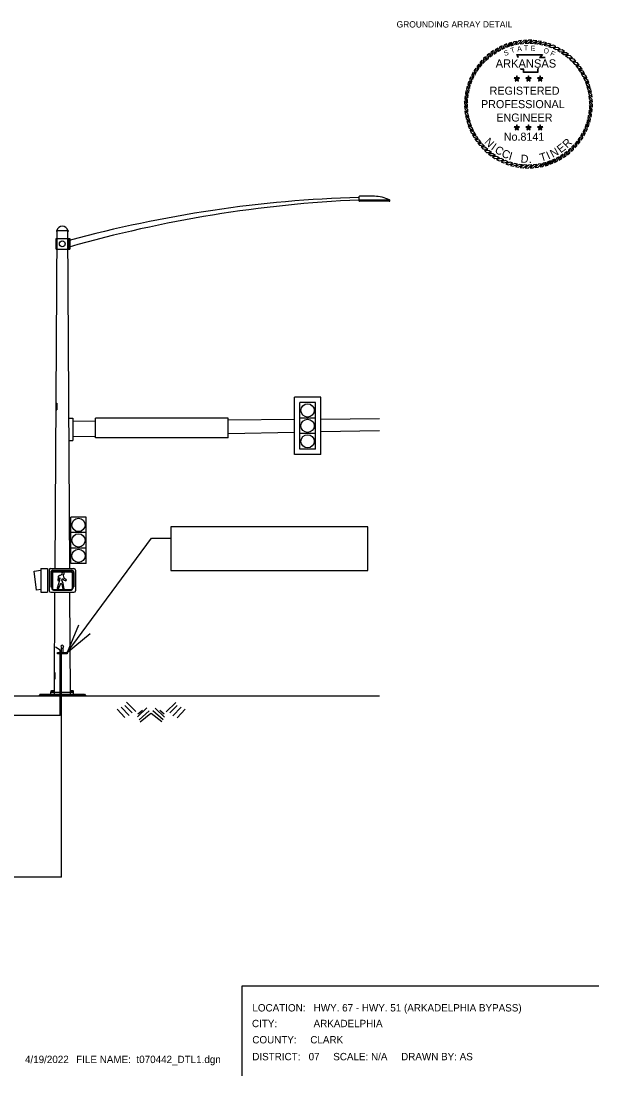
# Model space of a CAD drawing. Extents: x 418532 to 419834, y -565899 to -565296.
# Drawn here: x 419505 to 419834, y -565899 to -565297 of the extents above; entities that cross this region are included whole.
import ezdxf

# ---------------------------------------------------------------- set-up
doc = ezdxf.new("R2010")
doc.units = 0
for name, color, linetype in [('G-ANNO-SYMB', 7, 'Continuous'), ('G-ANNO-TEXT', 7, 'Continuous'), ('Level 10', 7, 'Continuous'), ('Level 57', 7, 'Continuous'), ('R_Draft', 7, 'Continuous'), ('T_Drafting', 7, 'Continuous')]:
    doc.layers.add(name, color=color, linetype=linetype)

msp = doc.modelspace()

# ---------------------------------------------------------------- linework, layer by layer
at = {"layer": 'G-ANNO-SYMB'}
for points in [[(419792.99, -565307.49), (419791.42, -565307.57), (419789.36, -565309.46), (419791.04, -565309.28)], [(419795.85, -565307.53), (419794.28, -565307.48), (419792.08, -565309.2), (419793.77, -565309.15)], [(419798.7, -565307.78), (419797.14, -565307.61), (419794.81, -565309.16), (419796.5, -565309.24)], [(419774.09, -565313.41), (419772.79, -565314.3), (419772.02, -565316.99), (419773.36, -565315.95)], [(419776.55, -565311.94), (419775.19, -565312.72), (419774.21, -565315.34), (419775.62, -565314.41)], [(419779.11, -565310.67), (419777.69, -565311.34), (419776.51, -565313.87), (419778, -565313.06)], [(419781.77, -565309.6), (419780.3, -565310.16), (419778.93, -565312.59), (419780.47, -565311.9)], [(419784.5, -565308.75), (419783, -565309.19), (419781.43, -565311.51), (419783.03, -565310.93)], [(419787.29, -565308.11), (419785.76, -565308.43), (419784.02, -565310.62), (419785.65, -565310.17)], [(419790.13, -565307.69), (419788.57, -565307.89), (419786.67, -565309.93), (419788.33, -565309.62)], [(419801.53, -565308.26), (419799.98, -565307.97), (419797.54, -565309.32), (419799.22, -565309.54)], [(419804.3, -565308.96), (419802.79, -565308.55), (419800.24, -565309.71), (419801.9, -565310.05)], [(419807.02, -565309.87), (419805.54, -565309.34), (419802.91, -565310.3), (419804.54, -565310.77)], [(419809.65, -565311), (419808.22, -565310.35), (419805.53, -565311.1), (419807.11, -565311.7)], [(419812.19, -565312.32), (419810.81, -565311.57), (419808.07, -565312.1), (419809.6, -565312.83)], [(419814.62, -565313.85), (419813.3, -565312.99), (419810.52, -565313.3), (419812, -565314.14)], [(419767.51, -565318.91), (419766.46, -565320.07), (419766.33, -565322.87), (419767.39, -565321.54)], [(419769.56, -565316.91), (419768.42, -565317.98), (419768.07, -565320.76), (419769.23, -565319.52)], [(419771.75, -565315.07), (419770.53, -565316.06), (419769.97, -565318.79), (419771.23, -565317.65)], [(419816.91, -565315.55), (419815.67, -565314.6), (419812.88, -565314.69), (419814.28, -565315.65)], [(419819.07, -565317.44), (419817.91, -565316.38), (419815.12, -565316.26), (419816.44, -565317.32)], [(419821.08, -565319.48), (419820, -565318.34), (419817.22, -565318), (419818.46, -565319.16)], [(419763.92, -565323.37), (419763.06, -565324.68), (419763.38, -565327.46), (419764.22, -565325.99)], [(419765.63, -565321.07), (419764.67, -565322.31), (419764.77, -565325.1), (419765.72, -565323.7)], [(419822.91, -565321.68), (419821.93, -565320.46), (419819.19, -565319.9), (419820.33, -565321.16)], [(419824.57, -565324.02), (419823.68, -565322.72), (419821, -565321.95), (419822.04, -565323.29)], [(419826.04, -565326.47), (419825.26, -565325.11), (419822.64, -565324.13), (419823.57, -565325.55)], [(419759.94, -565330.97), (419759.42, -565332.44), (419760.37, -565335.07), (419760.85, -565333.44)], [(419761.07, -565328.33), (419760.43, -565329.76), (419761.17, -565332.46), (419761.77, -565330.87)], [(419762.4, -565325.79), (419761.64, -565327.17), (419762.18, -565329.91), (419762.9, -565328.38)], [(419787.36, -565329.43), (419786.98, -565328.92), (419785.77, -565328.92), (419786.75, -565329.63)], [(419787.36, -565329.43), (419786.75, -565329.63), (419786.38, -565330.78), (419787.36, -565330.07)], [(419787.36, -565329.43), (419787.73, -565328.92), (419787.36, -565327.76), (419786.98, -565328.92)], [(419787.36, -565329.43), (419787.96, -565329.63), (419788.94, -565328.92), (419787.73, -565328.92)], [(419787.36, -565329.43), (419787.36, -565330.07), (419788.34, -565330.78), (419787.96, -565329.63)], [(419794.03, -565329.43), (419793.65, -565328.92), (419792.44, -565328.92), (419793.42, -565329.63)], [(419794.03, -565329.43), (419793.42, -565329.63), (419793.05, -565330.78), (419794.03, -565330.07)], [(419794.03, -565329.43), (419794.4, -565328.92), (419794.03, -565327.76), (419793.65, -565328.92)], [(419794.03, -565329.43), (419794.63, -565329.63), (419795.61, -565328.92), (419794.4, -565328.92)], [(419794.03, -565329.43), (419794.03, -565330.07), (419795.01, -565330.78), (419794.63, -565329.63)], [(419800.7, -565329.43), (419800.32, -565328.92), (419799.11, -565328.92), (419800.09, -565329.63)], [(419800.7, -565329.43), (419800.09, -565329.63), (419799.72, -565330.78), (419800.7, -565330.07)], [(419800.7, -565329.43), (419801.07, -565328.92), (419800.7, -565327.76), (419800.32, -565328.92)], [(419800.7, -565329.43), (419801.3, -565329.63), (419802.28, -565328.92), (419801.07, -565328.92)], [(419800.7, -565329.43), (419800.7, -565330.07), (419801.68, -565330.78), (419801.3, -565329.63)], [(419827.31, -565329.04), (419826.64, -565327.62), (419824.11, -565326.44), (419824.92, -565327.93)], [(419828.38, -565331.7), (419827.82, -565330.23), (419825.39, -565328.85), (419826.09, -565330.4)], [(419829.24, -565334.43), (419828.8, -565332.92), (419826.48, -565331.36), (419827.05, -565332.96)], [(419758.33, -565336.46), (419758.04, -565338), (419759.4, -565340.44), (419759.61, -565338.76)], [(419759.03, -565333.68), (419758.62, -565335.19), (419759.78, -565337.74), (419760.12, -565336.08)], [(419829.88, -565337.22), (419829.55, -565335.69), (419827.37, -565333.95), (419827.81, -565335.58)], [(419830.29, -565340.06), (419830.09, -565338.5), (419828.05, -565336.59), (419828.37, -565338.26)], [(419757.6, -565342.13), (419757.55, -565343.7), (419759.27, -565345.9), (419759.22, -565344.21)], [(419757.85, -565339.28), (419757.69, -565340.84), (419759.23, -565343.17), (419759.31, -565341.48)], [(419830.49, -565342.91), (419830.41, -565341.35), (419828.52, -565339.28), (419828.71, -565340.97)], [(419830.46, -565345.78), (419830.5, -565344.21), (419828.78, -565342.01), (419828.83, -565343.7)], [(419757.57, -565345), (419757.65, -565346.56), (419759.53, -565348.63), (419759.35, -565346.94)], [(419757.76, -565347.85), (419757.96, -565349.41), (419760.01, -565351.32), (419759.69, -565349.65)], [(419829.72, -565351.45), (419830.01, -565349.91), (419828.66, -565347.47), (419828.45, -565349.15)], [(419830.2, -565348.63), (419830.37, -565347.07), (419828.83, -565344.74), (419828.75, -565346.43)], [(419758.18, -565350.69), (419758.5, -565352.22), (419760.69, -565353.96), (419760.24, -565352.33)], [(419758.82, -565353.48), (419759.26, -565354.99), (419761.58, -565356.55), (419761, -565354.95)], [(419787.36, -565357.36), (419787.73, -565356.84), (419787.36, -565355.69), (419786.98, -565356.84)], [(419794.03, -565357.36), (419794.4, -565356.84), (419794.03, -565355.69), (419793.65, -565356.84)], [(419800.7, -565357.36), (419801.07, -565356.84), (419800.7, -565355.69), (419800.32, -565356.84)], [(419826.99, -565359.58), (419827.63, -565358.15), (419826.88, -565355.45), (419826.28, -565357.04)], [(419828.11, -565356.94), (419828.64, -565355.47), (419827.68, -565352.84), (419827.21, -565354.47)], [(419829.03, -565354.23), (419829.43, -565352.72), (419828.28, -565350.17), (419827.93, -565351.83)], [(419759.67, -565356.21), (419760.23, -565357.68), (419762.67, -565359.06), (419761.97, -565357.51)], [(419760.74, -565358.87), (419761.41, -565360.29), (419763.95, -565361.47), (419763.13, -565359.98)], [(419762.01, -565361.44), (419762.8, -565362.8), (419765.41, -565363.78), (419764.48, -565362.36)], [(419787.36, -565357.36), (419786.98, -565356.84), (419785.77, -565356.84), (419786.75, -565357.56)], [(419787.36, -565357.36), (419786.75, -565357.56), (419786.38, -565358.71), (419787.36, -565358)], [(419787.36, -565357.36), (419787.96, -565357.56), (419788.94, -565356.84), (419787.73, -565356.84)], [(419787.36, -565357.36), (419787.36, -565358), (419788.34, -565358.71), (419787.96, -565357.56)], [(419794.03, -565357.36), (419793.65, -565356.84), (419792.44, -565356.84), (419793.42, -565357.56)], [(419794.03, -565357.36), (419793.42, -565357.56), (419793.05, -565358.71), (419794.03, -565358)], [(419794.03, -565357.36), (419794.63, -565357.56), (419795.61, -565356.84), (419794.4, -565356.84)], [(419794.03, -565357.36), (419794.03, -565358), (419795.01, -565358.71), (419794.63, -565357.56)], [(419800.7, -565357.36), (419800.32, -565356.84), (419799.11, -565356.84), (419800.09, -565357.56)], [(419800.7, -565357.36), (419800.09, -565357.56), (419799.72, -565358.71), (419800.7, -565358)], [(419800.7, -565357.36), (419801.3, -565357.56), (419802.28, -565356.84), (419801.07, -565356.84)], [(419800.7, -565357.36), (419800.7, -565358), (419801.68, -565358.71), (419801.3, -565357.56)], [(419824.14, -565364.54), (419824.99, -565363.23), (419824.68, -565360.45), (419823.84, -565361.92)], [(419825.66, -565362.12), (419826.41, -565360.74), (419825.88, -565358), (419825.16, -565359.53)], [(419763.48, -565363.89), (419764.37, -565365.19), (419767.06, -565365.96), (419766.02, -565364.62)], [(419765.14, -565366.23), (419766.13, -565367.45), (419768.87, -565368.01), (419767.73, -565366.75)], [(419818.5, -565371), (419819.64, -565369.93), (419819.98, -565367.15), (419818.82, -565368.39)], [(419820.55, -565369), (419821.6, -565367.84), (419821.72, -565365.04), (419820.66, -565366.37)], [(419822.43, -565366.84), (419823.39, -565365.6), (419823.29, -565362.81), (419822.34, -565364.21)], [(419766.98, -565368.43), (419768.06, -565369.57), (419770.83, -565369.91), (419769.6, -565368.75)], [(419768.98, -565370.47), (419770.15, -565371.53), (419772.94, -565371.65), (419771.62, -565370.59)], [(419771.14, -565372.36), (419772.38, -565373.31), (419775.18, -565373.22), (419773.78, -565372.26)], [(419773.44, -565374.06), (419774.75, -565374.92), (419777.53, -565374.61), (419776.06, -565373.77)], [(419811.51, -565375.97), (419812.87, -565375.19), (419813.85, -565372.57), (419812.43, -565373.5)], [(419813.97, -565374.5), (419815.26, -565373.61), (419816.03, -565370.93), (419814.69, -565371.96)], [(419816.3, -565372.84), (419817.52, -565371.85), (419818.08, -565369.12), (419816.83, -565370.26)], [(419775.87, -565375.59), (419777.24, -565376.34), (419779.99, -565375.81), (419778.45, -565375.08)], [(419778.4, -565376.91), (419779.84, -565377.56), (419782.53, -565376.81), (419780.94, -565376.21)], [(419781.04, -565378.04), (419782.52, -565378.57), (419785.14, -565377.61), (419783.51, -565377.14)], [(419783.75, -565378.95), (419785.27, -565379.36), (419787.81, -565378.2), (419786.15, -565377.86)], [(419786.53, -565379.65), (419788.07, -565379.94), (419790.52, -565378.59), (419788.84, -565378.37)], [(419789.35, -565380.13), (419790.91, -565380.3), (419793.24, -565378.75), (419791.55, -565378.67)], [(419792.21, -565380.38), (419793.77, -565380.43), (419795.98, -565378.71), (419794.28, -565378.76)], [(419795.07, -565380.42), (419796.64, -565380.34), (419798.7, -565378.45), (419797.01, -565378.63)], [(419797.93, -565380.22), (419799.48, -565380.02), (419801.39, -565377.98), (419799.73, -565378.29)], [(419800.76, -565379.8), (419802.3, -565379.48), (419804.04, -565377.29), (419802.4, -565377.74)], [(419803.55, -565379.16), (419805.06, -565378.72), (419806.62, -565376.4), (419805.03, -565376.98)], [(419806.29, -565378.31), (419807.75, -565377.75), (419809.13, -565375.32), (419807.58, -565376.01)], [(419808.94, -565377.24), (419810.36, -565376.57), (419811.54, -565374.04), (419810.06, -565374.85)]]:
    msp.add_lwpolyline(points, close=True, dxfattribs=at)
for points in [[(419788.18, -565317.48), (419787.33, -565315.64), (419802.05, -565315.63), (419800.82, -565317.18), (419801.82, -565317.16), (419802.65, -565317.15), (419803.49, -565317.24)], [(419788.4, -565317.38), (419787.7, -565315.87), (419801.56, -565315.87), (419800.33, -565317.42), (419801.82, -565317.4), (419802.64, -565317.39), (419803.46, -565317.48)], [(419799.73, -565323.65), (419799.48, -565323.85), (419799.39, -565324.16), (419799.31, -565324.92), (419799.31, -565325.94), (419791.1, -565325.94), (419791.1, -565324.56), (419791.1, -565324.26), (419790.76, -565324.16), (419789.6, -565324.16), (419789.39, -565323.84)], [(419799.58, -565323.47), (419799.27, -565323.72), (419799.16, -565324.11), (419799.08, -565324.91), (419799.08, -565325.7), (419791.33, -565325.7), (419791.33, -565324.56), (419791.33, -565324.09), (419790.8, -565323.92), (419789.72, -565323.92), (419789.58, -565323.71)]]:
    msp.add_lwpolyline(points, dxfattribs=at)
at = {"layer": 'Level 57'}
for points in [[(419630.59, -565847.55), (419630.59, -565898.75)], [(419834.17, -565847.55), (419630.59, -565847.55)]]:
    msp.add_lwpolyline(points, dxfattribs=at)
at = {"layer": 'R_Draft'}
for p, q in [((419530.89, -565657.08), (419578.95, -565591.72)), ((419578.95, -565591.72), (419589.97, -565591.72))]:
    msp.add_line(p, q, dxfattribs=at)
msp.add_lwpolyline([(419589.97, -565610.25), (419702.39, -565610.25), (419702.39, -565585.34), (419589.97, -565585.34)], close=True, dxfattribs=at)
msp.add_lwpolyline([(419537.34, -565641.34), (419530.89, -565657.08), (419543.99, -565646.23)], dxfattribs=at)
at = {"layer": 'T_Drafting'}
for p, q in [((419697.33, -565396.95), (419697.33, -565397.22)), ((419697.33, -565397.22), (419697.33, -565399.07)), ((419706.15, -565396.57), (419697.71, -565396.57)), ((419714.89, -565398.73), (419697.33, -565398.73)), ((419714.6, -565399.44), (419697.71, -565399.44)), ((419714.98, -565398.97), (419714.98, -565399.07)), ((419524.99, -565416.17), (419523.86, -565609.16)), ((419524.71, -565420.67), (419531.37, -565420.67)), ((419524.71, -565426.8), (419524.71, -565420.67)), ((419524.84, -565416.17), (419531.49, -565416.17)), ((419524.84, -565416.17), (419524.84, -565416.64)), ((419532.47, -565609.16), (419531.34, -565416.17)), ((419531.37, -565420.67), (419532.51, -565420.67)), ((419531.49, -565416.17), (419531.49, -565416.64)), ((419532.04, -565426.8), (419532, -565420.67)), ((419532.51, -565420.67), (419532.51, -565426.8)), ((419524.75, -565426.8), (419531.41, -565426.8)), ((419531.41, -565426.8), (419532.51, -565426.8)), ((419660.5, -565544), (419660.5, -565511.23)), ((419675.65, -565511.23), (419660.5, -565511.23)), ((419675.65, -565544), (419675.65, -565511.23)), ((419524.41, -565514.72), (419525.01, -565514.72)), ((419525.01, -565514.72), (419524.99, -565518.51)), ((419663.65, -565540.85), (419663.65, -565514.38)), ((419672.5, -565514.38), (419663.65, -565514.38)), ((419672.5, -565540.85), (419672.5, -565514.38)), ((419524.39, -565518.51), (419524.99, -565518.51)), ((419531.97, -565523.22), (419534.21, -565523.22)), ((419534.21, -565523.22), (419534.21, -565536)), ((419622.72, -565523.19), (419547.1, -565523.19)), ((419547.1, -565534.53), (419547.1, -565523.19)), ((419622.72, -565534.53), (419622.72, -565523.19)), ((419660.5, -565524.06), (419622.72, -565524.39)), ((419672.5, -565523.2), (419663.65, -565523.2)), ((419709.07, -565523.64), (419675.65, -565523.93)), ((419547.1, -565525.05), (419534.21, -565525.17)), ((419709.07, -565530.39), (419675.65, -565531.08)), ((419532.04, -565536), (419534.21, -565536)), ((419547.1, -565533.72), (419534.21, -565533.99)), ((419622.72, -565534.53), (419547.1, -565534.53)), ((419660.5, -565531.39), (419622.72, -565532.17)), ((419672.5, -565532.03), (419663.65, -565532.03)), ((419672.5, -565540.85), (419663.65, -565540.85)), ((419675.65, -565544), (419660.5, -565544)), ((419533, -565606.24), (419533, -565579.77)), ((419541.85, -565579.77), (419533, -565579.77)), ((419541.85, -565606.24), (419541.85, -565579.77)), ((419541.85, -565588.59), (419533, -565588.59)), ((419541.85, -565597.42), (419533, -565597.42)), ((419541.85, -565606.24), (419533, -565606.24)), ((419512.13, -565610.68), (419515.92, -565610.07)), ((419513.39, -565621.37), (419512.13, -565610.68)), ((419515.92, -565609.16), (419515.92, -565622.64)), ((419515.92, -565609.16), (419519.7, -565609.16)), ((419519.7, -565609.16), (419519.7, -565622.64)), ((419520.6, -565610.07), (419520.6, -565621.69)), ((419521.51, -565609.16), (419534.82, -565609.16)), ((419521.55, -565611.36), (419521.55, -565619.49)), ((419522.19, -565611.58), (419522.19, -565620.46)), ((419522.49, -565611.58), (419522.49, -565620.46)), ((419522.84, -565610.07), (419533.46, -565610.07)), ((419523.1, -565610.68), (419533.23, -565610.68)), ((419523.1, -565610.98), (419533.23, -565610.98)), ((419533.84, -565611.58), (419533.84, -565620.46)), ((419534.14, -565611.58), (419534.14, -565620.46)), ((419534.75, -565611.36), (419534.75, -565619.49)), ((419535.73, -565610.07), (419535.73, -565621.73)), ((419521.55, -565619.49), (419522.18, -565619.49)), ((419534.14, -565619.49), (419534.75, -565619.49)), ((419515.92, -565621.06), (419513.39, -565621.37)), ((419515.92, -565622.64), (419519.7, -565622.64)), ((419521.55, -565622.64), (419534.82, -565622.64)), ((419523.1, -565621.06), (419533.23, -565621.06)), ((419523.1, -565621.37), (419533.23, -565621.37)), ((419523.78, -565622.64), (419523.44, -565680.86)), ((419532.89, -565680.86), (419532.55, -565622.64)), ((419527.47, -565653.82), (419527.79, -565654.68)), ((419526.94, -565693.03), (419526.94, -565657.87)), ((419527.79, -565785.2), (419527.79, -565657.87)), ((419523.51, -565668.41), (419524, -565668.41)), ((419524, -565668.41), (419523.98, -565672.19)), ((419523.49, -565672.19), (419523.98, -565672.19)), ((419515.56, -565680.86), (419514.93, -565681.49)), ((419515.56, -565680.86), (419540.77, -565680.86)), ((419521.7, -565679.76), (419534.63, -565679.76)), ((419521.7, -565680.86), (419521.7, -565679.76)), ((419521.85, -565678.97), (419523.42, -565678.97)), ((419521.85, -565679.76), (419521.85, -565678.97)), ((419522.07, -565678.65), (419523.2, -565678.65)), ((419522.07, -565678.97), (419522.07, -565678.65)), ((419522.38, -565679.76), (419522.38, -565678.97)), ((419522.91, -565679.76), (419522.91, -565678.97)), ((419523.2, -565678.97), (419523.2, -565678.65)), ((419523.42, -565679.76), (419523.42, -565678.97)), ((419532.92, -565678.97), (419534.48, -565678.97)), ((419532.92, -565679.76), (419532.92, -565678.97)), ((419533.07, -565678.97), (419533.07, -565678.65)), ((419533.07, -565678.65), (419534.33, -565678.65)), ((419533.42, -565679.76), (419533.42, -565678.97)), ((419533.95, -565679.76), (419533.95, -565678.97)), ((419534.33, -565678.97), (419534.33, -565678.65)), ((419534.48, -565679.76), (419534.48, -565678.97)), ((419534.63, -565680.86), (419534.63, -565679.76)), ((419540.77, -565680.86), (419541.4, -565681.49)), ((419709.07, -565681.87), (419149.59, -565681.87)), ((419514.93, -565681.49), (419541.4, -565681.49)), ((419514.93, -565681.87), (419514.93, -565681.49)), ((419541.4, -565681.87), (419541.4, -565681.49)), ((419570.1, -565690.73), (419564.74, -565685.36)), ((419587.47, -565690.84), (419592.83, -565685.48)), ((419563.8, -565694.23), (419559.37, -565689.33)), ((419566.37, -565693.06), (419561.71, -565688.16)), ((419568, -565691.43), (419563.8, -565687.23)), ((419571.03, -565693.76), (419576.39, -565688.63)), ((419571.26, -565692.13), (419573.83, -565690.03)), ((419571.96, -565695.39), (419577.79, -565690.26)), ((419572.66, -565696.56), (419578.73, -565691.66)), ((419584.9, -565696.68), (419578.84, -565691.78)), ((419585.6, -565695.51), (419579.78, -565690.38)), ((419586.54, -565693.88), (419581.17, -565688.74)), ((419586.3, -565692.24), (419583.74, -565690.14)), ((419589.57, -565691.54), (419593.76, -565687.34)), ((419591.2, -565693.18), (419595.86, -565688.28)), ((419593.76, -565694.34), (419598.19, -565689.44)), ((419526.94, -565693.03), (419451.45, -565693.03)), ((419527.79, -565785.2), (419288.41, -565785.2))]:
    msp.add_line(p, q, dxfattribs=at)
for points in [[(419525.77, -565613.59), (419525.65, -565615.91), (419526.37, -565615.91), (419526.55, -565614.38), (419526.72, -565614.38), (419526.54, -565615.74), (419526.54, -565615.98), (419525.32, -565620.28), (419525.32, -565620.44), (419525.81, -565620.82), (419526.02, -565620.65), (419527.31, -565617.4), (419527.84, -565618.01), (419528.47, -565620.88), (419529.28, -565620.61), (419528.71, -565617.57), (419527.93, -565615.76), (419528.44, -565614.84), (419528.8, -565615.51), (419530.24, -565616.07), (419530.52, -565615.68), (419529.15, -565614.53), (419528.8, -565613.08), (419528.86, -565612.87), (419528.86, -565612.64), (419528.93, -565612.6)], [(419526.94, -565657.08), (419526.94, -565655.63), (419524.33, -565653.89)], [(419527.79, -565657.08), (419527.79, -565654.63), (419527.79, -565654.91), (419527.75, -565654.95), (419527.76, -565654.94)], [(419528.76, -565653.82), (419528.46, -565654.61), (419528.46, -565654.61), (419528.46, -565657.08)]]:
    msp.add_lwpolyline(points, dxfattribs=at)
msp.add_lwpolyline([(419525.44, -565657.08), (419530.89, -565657.08), (419530.89, -565657.87), (419525.44, -565657.87)], close=True, dxfattribs=at)
for centre, radius in [((419528.17, -565423.73), 1.66), ((419668.07, -565518.8), 3.78), ((419668.07, -565527.63), 3.78), ((419668.07, -565536.45), 3.78), ((419537.42, -565584.2), 3.78), ((419537.42, -565593.02), 3.78), ((419537.42, -565601.84), 3.78)]:
    msp.add_circle(centre, radius, dxfattribs=at)
for centre, radius, start, end in [((419718.38, -566105.7), 708.8, 91.70171, 105.2447), ((419697.71, -565396.95), 0.378, 90, 180), ((419705.36, -565418.96), 22.41, 65.20004, 87.96446), ((419727.94, -566108.25), 710.19, 92.47054, 106.01353), ((419697.71, -565399.07), 0.378, 180, 270), ((419714.6, -565399.07), 0.378, 270, 0), ((419714.6, -565398.97), 0.378, 360, 65.20004), ((419528.17, -565416.91), 3.26, 13.14148, 166.85852), ((419521.51, -565610.07), 0.907, 90, 180), ((419522.84, -565611.36), 1.29, 90, 180), ((419523.1, -565611.58), 0.907, 90, 180), ((419523.1, -565611.58), 0.605, 90, 180), ((419533.23, -565611.58), 0.907, 0, 90), ((419533.23, -565611.58), 0.605, 0, 90), ((419533.46, -565611.36), 1.29, 0, 90), ((419534.82, -565610.07), 0.907, 0, 90), ((419523.1, -565620.46), 0.907, 180, 270), ((419523.1, -565620.46), 0.605, 180, 270), ((419533.23, -565620.46), 0.605, 270, 0), ((419533.23, -565620.46), 0.907, 270, 0), ((419521.55, -565621.69), 0.945, 180, 270), ((419534.82, -565621.73), 0.907, 270, 0), ((419528.12, -565653.52), 0.721, 336.80141, 203.80594), ((419528.12, -565653.52), 0.721, 239.53446, 239.74356)]:
    msp.add_arc(centre, radius, start, end, dxfattribs=at)
msp.add_ellipse((419528.62, -565611.91), major_axis=(0, -0.761), ratio=0.9, start_param=0.463156, end_param=5.216339, dxfattribs=at)
msp.add_spline([(419528.02, -565612.28), (419527.95, -565612.41), (419527.84, -565612.47), (419527.7, -565612.58), (419527.56, -565612.7), (419527.01, -565612.98), (419526.74, -565613.1), (419526.48, -565613.21), (419526.14, -565613.4), (419525.97, -565613.46), (419525.77, -565613.59)], degree=3, dxfattribs=at)

# ---------------------------------------------------------------- texts
at = {"layer": 'G-ANNO-SYMB'}
for s, height, rotation, p in [('S', 2.9, 19.77256, (419780.52, -565316.52)), ('T', 2.9, 16.90148, (419784.21, -565314.86)), ('A', 2.9, 8.67877, (419787.74, -565313.94)), ('T', 2.9, 1.47887, (419791.48, -565313.36)), ('E', 2.9, 356.67203, (419795.2, -565313.45)), ('O', 2.9, 341.2218, (419802.24, -565314.45)), ('F', 2.9, 335.36282, (419806.16, -565315.98)), ('N', 4.59, 315.26758, (419768.55, -565365.95)), ('I', 4.59, 324.21406, (419772.28, -565369.65)), ('E', 4.59, 37.64979, (419812.45, -565372.13)), ('R', 4.59, 45.47796, (419816.12, -565369.36)), ('C', 4.59, 328.68731, (419774.35, -565371.27)), ('C', 4.59, 336.51548, (419778.25, -565373.69)), ('I', 4.59, 344.34365, (419782.45, -565375.56)), ('D', 4.59, 356.64507, (419789.45, -565377.31)), ('T', 4.59, 16.77466, (419801.21, -565376.84)), ('I', 4.59, 24.23006, (419805.41, -565375.64)), ('N', 4.59, 28.7033, (419807.85, -565374.65)), ('.', 4.59, 4.84601, (419794.25, -565377.62))]:
    msp.add_text(s, height=height, rotation=rotation, dxfattribs=at).set_placement(p)
for s, height, p in [('ARKANSAS', 4.737, (419775.31, -565323.12)), ('REGISTERED', 4.585, (419771.86, -565338.58)), ('PROFESSIONAL', 4.5855, (419766.95, -565346.25)), ('ENGINEER', 4.585, (419775.69, -565353.92)), ('No.8141', 4.567, (419779.96, -565364.85))]:
    msp.add_text(s, height=height, dxfattribs=at).set_placement(p)
at = {"layer": 'G-ANNO-TEXT'}
msp.add_text('GROUNDING ARRAY DETAIL', height=3.6, dxfattribs=at).set_placement((419718.81, -565300.21))
at = {"layer": 'Level 10'}
for s, p in [('LOCATION:   HWY. 67 - HWY. 51 (ARKADELPHIA BYPASS)', (419636.58, -565861.97)), ('CITY:', (419636.32, -565870.93)), (' ARKADELPHIA', (419669.92, -565870.93)), ('COUNTY:     CLARK', (419636.53, -565880.2)), ('DISTRICT:   07     SCALE: N/A     DRAWN BY: AS', (419636.51, -565889.83)), ('4/19/2022', (419506.87, -565891.43)), ('  FILE NAME: ', (419532.97, -565891.43)), ('t070442_DTL1.dgn', (419570.46, -565891.43))]:
    msp.add_text(s, height=4.2, rotation=360, dxfattribs=at).set_placement(p)

doc.saveas('drawing.dxf')
